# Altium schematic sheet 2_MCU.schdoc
size 309 x 223 mm; Symbol: Artery_A4; Device: Artery_A4; Company: Artery Technology; Drawed: SD; Version: 1.2; Page Size: A4; @Project Name: AT_START_F421_V1.2; @Page Count: 4; @Update Date: 2023-09-07; @Schematic Name: AT_START_F421; @Page No: 2; @Page Name: MCU
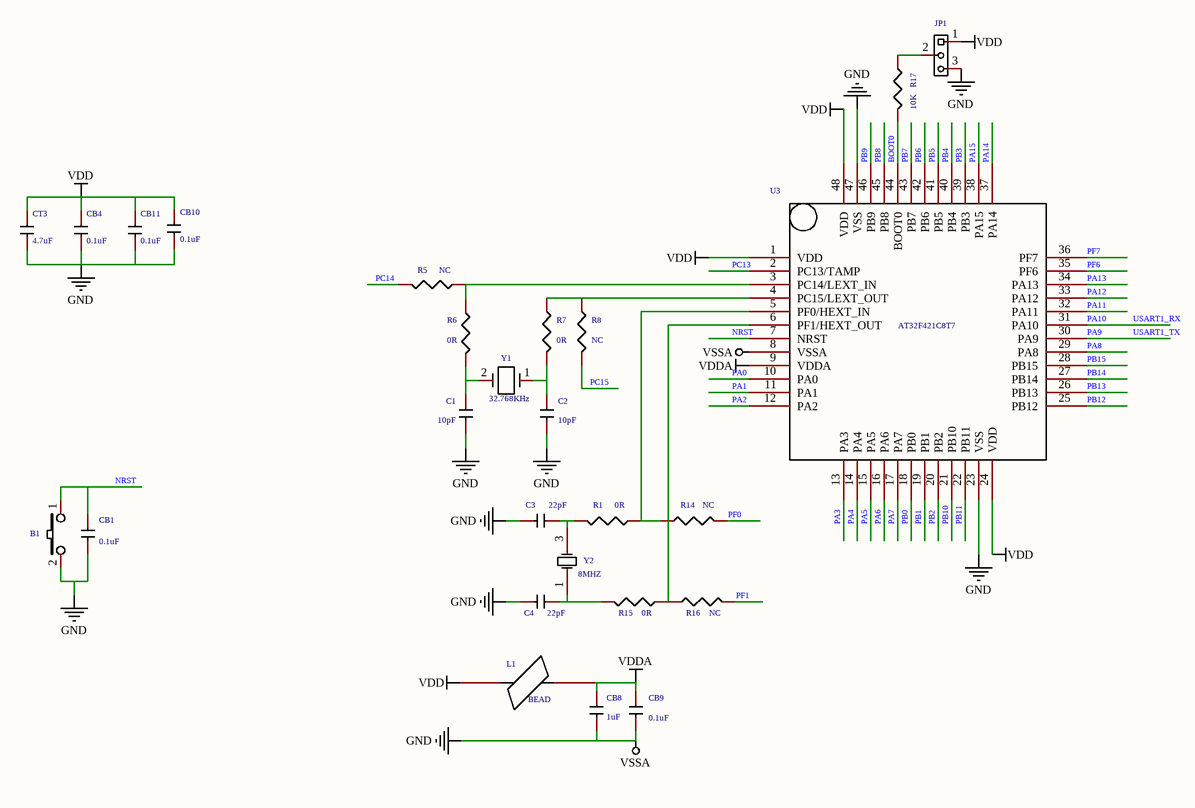
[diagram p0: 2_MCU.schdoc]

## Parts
B1  PB,BLACK,SMD_2P  [KEY_SOP_6*6]  (value not drawn)
C1  10pF  [C0603]
C2  10pF  [C0603]
C3  22pF  [C0603]
C4  22pF  [C0603]
CB1  0.1uF  [C0603]
CB4  0.1uF  [C0603]
CB8  1uF  [C0603]
CB9  0.1uF  [C0603]
CB10  0.1uF  [C0603]
CB11  0.1uF  [C0603]
CT3  4.7uF  [C0603]
JP1  1X3P_2.54M  [HDR1X3]  (value not drawn)
L1  BEAD  [r0603]
R1  0R  [SB-PAD]
R5  NC  [SB-PAD]
R6  0R  [SB-PAD]
R7  0R  [SB-PAD]
R8  NC  [SB-PAD]
R14  NC  [SB-PAD]
R15  0R  [SB-PAD]
R16  NC  [SB-PAD]
R17  10K  [r0603]
U3  AT32F421C8T7  [LQFP48]
Y1  32.768KHz  [XTAL_SOP - FC-12M]
Y2  8MHZ  [SMD_5032_4P]

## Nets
GND: B1.2 C1.2 C2.2 C3.2 C4.2 CB1.2 CB4.2 CB8.2 CB9.2 CB10.2 CB11.2 CT3.2 JP1.3 U3.8(VSSA) U3.23(VSS) U3.47(VSS)  [also labelled VSSA]
VDD: CB4.1 CB10.1 CB11.1 CT3.1 JP1.1 L1.1 U3.1(VDD) U3.24(VDD) U3.48(VDD)
VDDA: CB8.1 CB9.1 L1.2 U3.9(VDDA)
BOOT0: R17.2 U3.44(BOOT0)
NRST: B1.1 CB1.1 U3.7(NRST)
PA0: U3.10(PA0)
PA1: U3.11(PA1)
PA2: U3.12(PA2)
PA3: U3.13(PA3)
PA4: U3.14(PA4)
PA5: U3.15(PA5)
PA6: U3.16(PA6)
PA7: U3.17(PA7)
PA8: U3.29(PA8)
PA9: U3.30(PA9)  [also labelled USART1_TX]
PA10: U3.31(PA10)  [also labelled USART1_RX]
PA11: U3.32(PA11)
PA12: U3.33(PA12)
PA13: U3.34(PA13)
PA14: U3.37(PA14)
PA15: U3.38(PA15)
PB0: U3.18(PB0)
PB1: U3.19(PB1)
PB2: U3.20(PB2)
PB3: U3.39(PB3)
PB4: U3.40(PB4)
PB5: U3.41(PB5)
PB6: U3.42(PB6)
PB7: U3.43(PB7)
PB8: U3.45(PB8)
PB9: U3.46(PB9)
PB10: U3.21(PB10)
PB11: U3.22(PB11)
PB12: U3.25(PB12)
PB13: U3.26(PB13)
PB14: U3.27(PB14)
PB15: U3.28(PB15)
PC13: U3.2(PC13/TAMP)
PC14: R5.2
PC15: R8.2
PF0: R14.2
PF1: R16.2
PF6: U3.35(PF6)
PF7: U3.36(PF7)
NetC1_1: C1.1 R6.2 Y1.2
NetC2_1: C2.1 R7.2 Y1.1
NetC3_1: C3.1 R1.2 Y2.3(OSC2)
NetC4_1: C4.1 R15.2 Y2.1(OSC1)
NetJP1_2: JP1.2 R17.1
NetR1_1: R1.1 R14.1 U3.5(PF0/HEXT_IN)
NetR5_1: R5.1 R6.1 U3.3(PC14/LEXT_IN)
NetR7_1: R7.1 R8.1 U3.4(PC15/LEXT_OUT)
NetR15_1: R15.1 R16.1 U3.6(PF1/HEXT_OUT)

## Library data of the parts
B1 = PB,BLACK,SMD_2P: 贴片按键6*6*5 黑色; Symbol: Push_Bottom,Blue,SMD_2P; Add into BOM: yes
C1 C2 = 10pF: 贴片陶瓷电容 10pF,50V,COG,5%,0603; Symbol: 10pF,50V,5%,SMD0603; Add into BOM: yes
C3 C4 = 22pF: 贴片陶瓷电容 22pF,50V,COG,5%,0603; Symbol: 10pF,50V,5%,SMD0603; Add into BOM: yes
CB1 = 0.1uF: 贴片陶瓷电容 0.1uF,25V,X5R,10%,0603; Symbol: 0.1uF,50V,20%,SMD0603; Add into BOM: yes
CB4 CB10 CB11 = 0.1uF: 贴片陶瓷电容 0.1uF,25V,X5R,10%,0603; Symbol: 0.1uF,25V,20%,SMD0402; Add into BOM: yes
CB8 = 1uF: 贴片陶瓷电容 1uF,25V,X5R,10%,0603; Symbol: 0.1uF,50V,20%,SMD0603; Add into BOM: yes
CB9 = 0.1uF: 贴片陶瓷电容 0.1uF,25V,X5R,10%,0603; Symbol: 0.1uF,50V,20%,SMD0603; Add into BOM: yes; NAME: 2; Pin Type: IN
CT3 = 4.7uF: 贴片陶瓷电容 4.7uF,25V,X5R,10%,0603; Symbol: 0.1uF,25V,20%,SMD0402; Add into BOM: yes
JP1 = 1X3P_2.54M: 单排直插针1*3P 2.54mm（黑色）; Symbol: 1X3P,Male,DIP_2.54; Add into BOM: yes
L1 = BEAD: 贴片磁珠 600 Ohm@100Mhz 200mA 0603; Add into BOM: yes
R1 R6 R7 R15 = 0R: 贴片电阻0R,1/10W,5%,0603; Symbol: 0,1/10W,1%,SMD0603; Add into BOM: yes
R5 R8 R14 R16 = NC: 贴片电阻0R,1/10W,5%,0603; Symbol: 0,1/10W,1%,SMD0603; Add into BOM: yes
R17 = 10K: 贴片电阻10K,1/10W,5%,0603; Symbol: 10K,1/10W,1%,SMD0603; Add into BOM: yes
U3 = AT32F421C8T7: AT32F421Cx; Add into BOM: yes
Y1 = 32.768KHz: 32.768KHz贴片晶振 TZ2528C 2012 12.5pf 20ppm; Symbol: 32.768KHz,CRY,30PPM,Size_3X8; Add into BOM: yes
Y2 = 8MHz: 8MHz贴片晶振 TZ0211E 5032_4P  20PF 15ppm; Symbol: SMD-5032_4P  8MHZ 20PF 10PPM; Add into BOM: yes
